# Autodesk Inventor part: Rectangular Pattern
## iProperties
Shininess: 64.0
Length Units: 11269
Angle Units: 11279
Time Units: 11290
Mass Units: 11283
Length Display Precision: 3
Angle Display Precision: 2
Compacted: True
Part Number: Rectangular Pattern
Document SubType Name: Modeling
Created: 2002-12
Designer: deepak
Density: 1 g/cm^3
Density: 0.0
Volumn: 0.0
Area: 0.0
PropertySet Name: Model Information
Control State: 0
Master: False
Checked Out: False
Author: deepak
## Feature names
1. Extrusion1
2. Extrusion2
3. Extrusion3
4. Extrusion4
